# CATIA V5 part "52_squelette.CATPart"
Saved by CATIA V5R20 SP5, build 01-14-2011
Part number: 52_squelette
Publications: "Plan.1", "Plan yz", "Plan.3", "Point.1"
Bounding box of the stored display mesh (mm): x 0 to 0, y 140.362 to 140.362, z 111 to 111
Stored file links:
  C:\Documents and Settings\anizard\Bureau\13\52_squelette.CATPart
  C:\Documents and Settings\anizard\Bureau\13\anizard.CATProduct
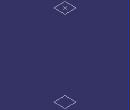
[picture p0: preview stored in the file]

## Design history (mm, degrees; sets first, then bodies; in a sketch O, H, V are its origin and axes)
Set1
  Plane1: linked copy from another document
  Point1: linked copy from another document
Body1 (main body)
  Plane2: type Offset, RefPlane Plane1, Offset 16
  Plane3: type Offset, RefPlane Plane1, Offset 4
  Point2: type OnPlane, Support Plane2, RefPoint Point1, H 0, V 0, Direction (1, 0, 0)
